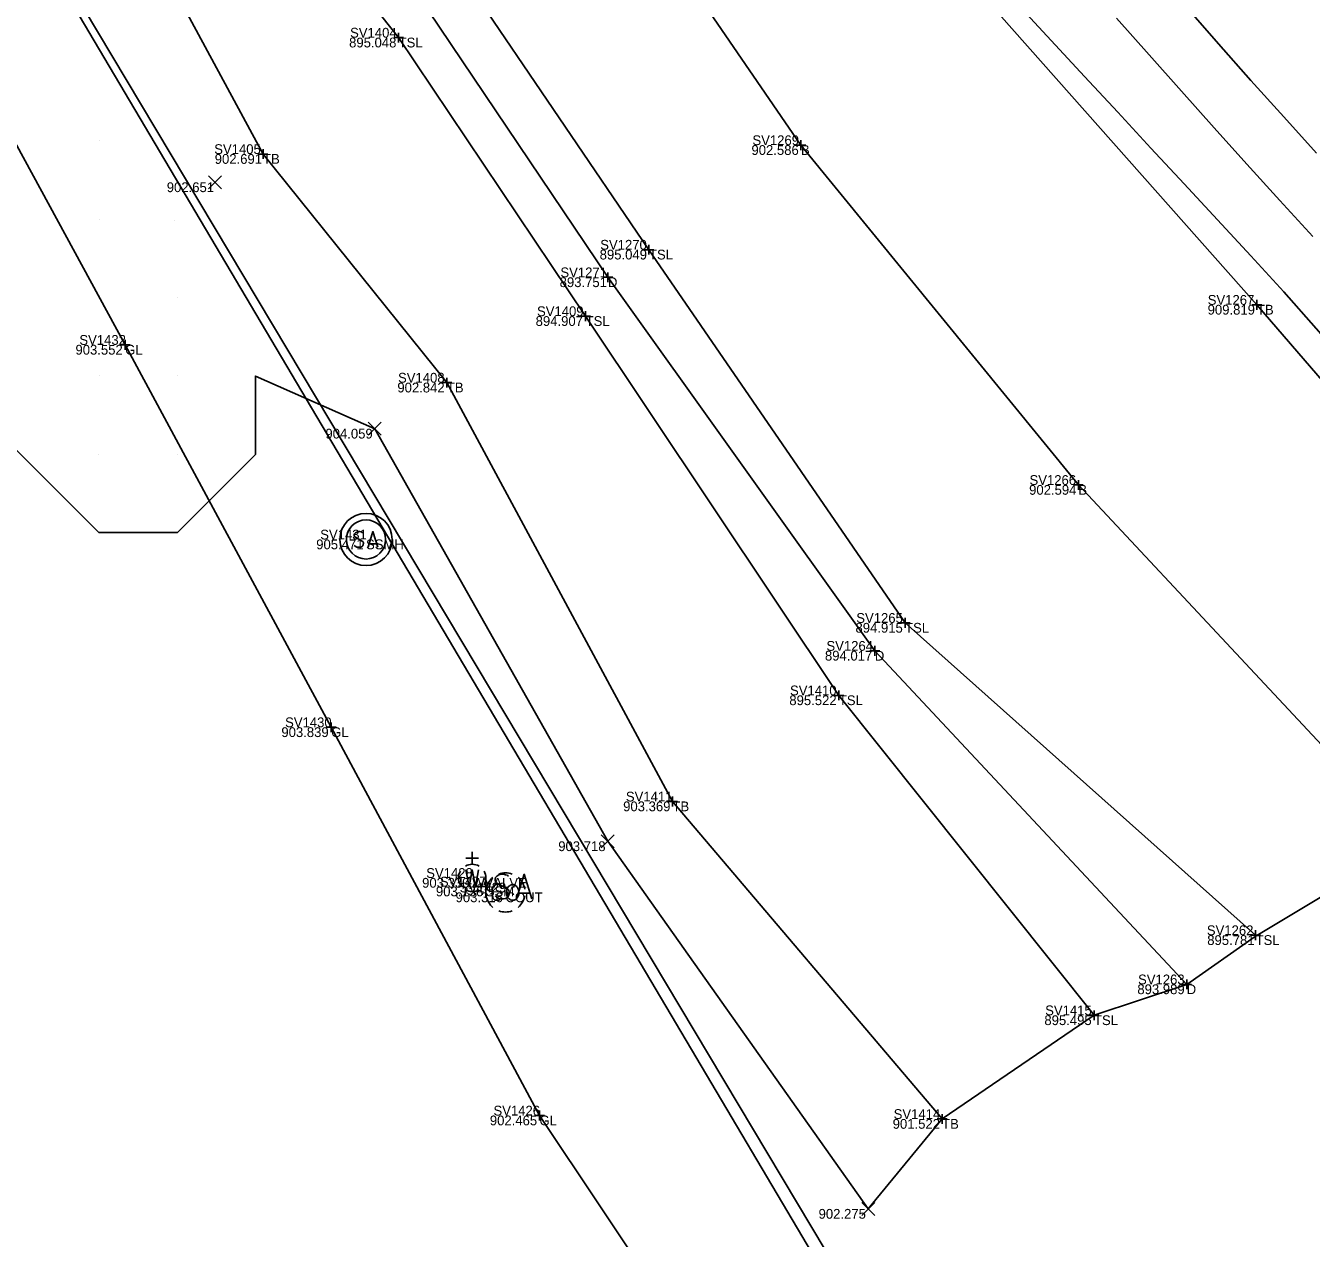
# Model space of a CAD drawing. Extents: x 1918148 to 1919797, y 624701 to 627089.
# Drawn here: x 1918904 to 1919035.3, y 625387.1 to 625511 of the extents above; entities that cross this region are included whole.
import ezdxf

# ---------------------------------------------------------------- set-up
doc = ezdxf.new("R2010")
doc.units = 0
for name, color, linetype in [('DR_X_Cells', 7, 'Continuous'), ('DR_X_Ditch', 7, 'Continuous'), ('DT_X_Terrain_Boundary', 7, 'Continuous'), ('GK_Drainage_Nodes', 7, 'Continuous'), ('Ground Shots', 7, 'Continuous'), ('PM_X_Edge_Line', 7, 'Continuous'), ('PV_X_Shoulder_Aggregate', 7, 'Continuous'), ('RD_X_Concrete_Pad', 7, 'Continuous'), ('RD_X_Fence', 7, 'Continuous'), ('SV_X_Break_Lines', 7, 'Continuous'), ('SV_X_Random_Point', 7, 'Continuous'), ('SV_X_Shot_Marker', 7, 'Continuous'), ('SV_X_Text_Comment', 7, 'Continuous'), ('SV_X_Text_Elevation', 7, 'Continuous'), ('SV_X_Text_Name', 7, 'Continuous'), ('SV_X_Toe_of_Slope', 7, 'Continuous'), ('SV_X_Top_of_Bank', 7, 'Continuous'), ('UT_X_Gas', 7, 'Continuous'), ('UT_X_Overhead_Combined', 7, 'Continuous'), ('UT_X_Sanitary_Cells', 7, 'Continuous'), ('UT_X_Water_Cells', 7, 'Continuous')]:
    doc.layers.add(name, color=color, linetype=linetype)

msp = doc.modelspace()

# ---------------------------------------------------------------- linework, layer by layer
at = {"layer": 'DR_X_Cells'}
msp.add_line((1918953, 625422.45), (1918953, 625422.45), dxfattribs=at)
for points in [[(1918952.59, 625422.93), (1918952.52, 625423.07), (1918952.46, 625423.15), (1918952.4, 625423.2), (1918952.35, 625423.22), (1918952.21, 625423.25), (1918952.07, 625423.25), (1918951.89, 625423.2), (1918951.79, 625423.12), (1918951.74, 625423.06), (1918951.69, 625422.97), (1918951.65, 625422.83), (1918951.64, 625422.58), (1918951.64, 625422.39), (1918951.64, 625422.27), (1918951.65, 625422.15), (1918951.69, 625421.95), (1918951.7, 625421.91), (1918951.75, 625421.82), (1918951.8, 625421.76), (1918951.89, 625421.7), (1918951.97, 625421.67), (1918952.07, 625421.65), (1918952.18, 625421.65), (1918952.3, 625421.66), (1918952.33, 625421.67), (1918952.38, 625421.7), (1918952.43, 625421.75), (1918952.5, 625421.81), (1918952.55, 625421.89), (1918952.59, 625421.95)], [(1918953.61, 625423.24), (1918953.57, 625423.22), (1918953.53, 625423.21), (1918953.47, 625423.17), (1918953.43, 625423.15), (1918953.37, 625423.1), (1918953.32, 625423.05), (1918953.29, 625423.02), (1918953.25, 625422.97), (1918953.19, 625422.84), (1918953.14, 625422.72), (1918953.11, 625422.61), (1918953.1, 625422.44), (1918953.11, 625422.27), (1918953.15, 625422.14), (1918953.19, 625422.04), (1918953.22, 625421.99), (1918953.25, 625421.93), (1918953.3, 625421.86), (1918953.34, 625421.82), (1918953.38, 625421.79), (1918953.43, 625421.75), (1918953.49, 625421.71), (1918953.61, 625421.66), (1918953.67, 625421.65), (1918953.79, 625421.65), (1918953.85, 625421.66), (1918953.9, 625421.67), (1918953.96, 625421.7), (1918954.02, 625421.74), (1918954.06, 625421.76), (1918954.1, 625421.79), (1918954.14, 625421.82), (1918954.17, 625421.87), (1918954.2, 625421.91), (1918954.22, 625421.95), (1918954.25, 625421.99), (1918954.29, 625422.06), (1918954.32, 625422.15), (1918954.35, 625422.25), (1918954.36, 625422.34), (1918954.36, 625422.35), (1918954.36, 625422.44), (1918954.36, 625422.52), (1918954.35, 625422.62), (1918954.32, 625422.72), (1918954.3, 625422.79), (1918954.26, 625422.88), (1918954.22, 625422.96), (1918954.16, 625423.03), (1918954.11, 625423.08), (1918954.06, 625423.13), (1918954.01, 625423.17), (1918953.93, 625423.21), (1918953.86, 625423.24), (1918953.78, 625423.25), (1918953.69, 625423.25), (1918953.61, 625423.24)]]:
    msp.add_lwpolyline(points, dxfattribs=at)
for start, end in [(70.0577, 110.1061), (130.0806, 170.0721), (10.0169, 50.0392), (190.0169, 230.0392), (310.0114, 350.0264), (250.0577, 290.0473)]:
    msp.add_arc((1918953, 625422.45), 2, start, end, dxfattribs=at)
at = {"layer": 'DR_X_Ditch'}
msp.add_lwpolyline([(1919022.6, 625413.06), (1918990.74, 625447.13), (1918963.47, 625485.28), (1918945.14, 625512.5), (1918919.46, 625550.94), (1918912.25, 625562.33), (1918904.47, 625574.16)], dxfattribs=at)
at = {"layer": 'DT_X_Terrain_Boundary'}
msp.add_lwpolyline([(1918871.72, 625515.38), (1918879.45, 625499.23), (1918887.28, 625491.32), (1918895.46, 625475.2), (1918903.47, 625467.18), (1918911.46, 625459.22), (1918919.47, 625459.21), (1918927.47, 625467.19), (1918927.45, 625475.19), (1918939.64, 625469.81), (1918963.45, 625427.67), (1918990.06, 625390.12), (1918997.61, 625399.31), (1919013.13, 625409.9), (1919022.6, 625413.06), (1919029.61, 625417.96), (1919045.66, 625427.6)], dxfattribs=at)
at = {"layer": 'GK_Drainage_Nodes'}
for p, q in [((1918938.75, 625460.5), (1918938.75, 625460.5)), ((1918938.75, 625458.5), (1918938.75, 625458.5)), ((1918938.75, 625458.5), (1918938.75, 625458.5)), ((1918938.75, 625458.5), (1918938.75, 625458.5)), ((1918938.75, 625456.5), (1918938.75, 625456.5))]:
    msp.add_line(p, q, dxfattribs=at)
msp.add_circle((1918938.75, 625458.5), 2, dxfattribs=at)
at = {"layer": 'Ground Shots'}
for p, q in [((1918911.53, 625499.21), (1918911.53, 625499.21)), ((1918911.48, 625491.2), (1918911.48, 625491.2)), ((1918919.17, 625491.05), (1918919.17, 625491.05)), ((1918911.48, 625483.22), (1918911.48, 625483.22)), ((1918919.44, 625483.24), (1918919.44, 625483.24)), ((1918911.47, 625475.21), (1918911.47, 625475.21)), ((1918919.44, 625475.23), (1918919.44, 625475.23)), ((1918927.45, 625475.19), (1918927.45, 625475.19)), ((1918911.45, 625467.19), (1918911.45, 625467.19)), ((1918919.48, 625467.21), (1918919.48, 625467.21)), ((1918927.47, 625467.19), (1918927.47, 625467.19)), ((1918911.46, 625459.22), (1918911.46, 625459.22)), ((1918919.47, 625459.21), (1918919.47, 625459.21))]:
    msp.add_line(p, q, dxfattribs=at)
at = {"layer": 'PM_X_Edge_Line'}
msp.add_lwpolyline([(1919022.56, 625512.89), (1919025.85, 625509.13), (1919029.16, 625505.38), (1919032.51, 625501.67), (1919035.86, 625497.96)], dxfattribs=at)
at = {"layer": 'PV_X_Shoulder_Aggregate'}
msp.add_lwpolyline([(1919068.79, 625442.49), (1919065.49, 625446.24), (1919062.19, 625450), (1919058.9, 625453.75), (1919055.6, 625457.51), (1919052.3, 625461.26), (1919049.01, 625465.02), (1919045.71, 625468.77), (1919042.42, 625472.53), (1919039.12, 625476.29), (1919035.82, 625480.04), (1919032.53, 625483.8), (1919029.14, 625487.48), (1919025.75, 625491.14), (1919022.35, 625494.81), (1919018.95, 625498.47), (1919015.55, 625502.14), (1919012.16, 625505.8), (1919008.76, 625509.47), (1919005.36, 625513.13)], dxfattribs=at)
at = {"layer": 'RD_X_Concrete_Pad'}
msp.add_lwpolyline([(1919015.43, 625511.75), (1919018.75, 625508.01), (1919022.07, 625504.28), (1919025.4, 625500.55), (1919028.76, 625496.84), (1919032.12, 625493.14), (1919035.49, 625489.45)], dxfattribs=at)
at = {"layer": 'RD_X_Fence'}
msp.add_lwpolyline([(1918745.79, 625786.43), (1918772.78, 625741.75), (1918796.76, 625701.53), (1918837.42, 625633.44), (1918845.82, 625619.99), (1919000.61, 625360.91)], dxfattribs=at)
at = {"layer": 'SV_X_Break_Lines'}
msp.add_lwpolyline([(1919045.66, 625427.6), (1919011.53, 625464.07), (1918983.19, 625498.78), (1918965.77, 625524.18), (1918940.24, 625565.26), (1918931.64, 625587.04), (1918915.78, 625618.09), (1918902.81, 625643.72), (1918894.51, 625661.89), (1918884.61, 625712.49), (1918865.54, 625771.79)], dxfattribs=at)
at = {"layer": 'SV_X_Random_Point'}
for p, q in [((1918922.66, 625494.31), (1918923.99, 625495.65)), ((1918922.66, 625495.65), (1918923.99, 625494.31)), ((1918938.98, 625469.14), (1918940.31, 625470.47)), ((1918938.98, 625470.47), (1918940.31, 625469.14)), ((1918962.78, 625427.01), (1918964.11, 625428.34)), ((1918962.78, 625428.34), (1918964.11, 625427.01)), ((1918989.4, 625389.45), (1918990.73, 625390.79)), ((1918989.4, 625390.79), (1918990.73, 625389.45))]:
    msp.add_line(p, q, dxfattribs=at)
at = {"layer": 'SV_X_Shot_Marker'}
for p, q in [((1918941.58, 625509.76), (1918942.58, 625509.76)), ((1918942.08, 625510.26), (1918942.08, 625509.26)), ((1918942.08, 625509.76), (1918942.08, 625509.76)), ((1918983.19, 625499.28), (1918983.19, 625498.28)), ((1918927.73, 625497.87), (1918928.73, 625497.87)), ((1918928.23, 625498.37), (1918928.23, 625497.37)), ((1918928.23, 625497.87), (1918928.23, 625497.87)), ((1918982.69, 625498.78), (1918983.69, 625498.78)), ((1918983.19, 625498.78), (1918983.19, 625498.78)), ((1918967.66, 625488.6), (1918967.66, 625487.6)), ((1918967.16, 625488.1), (1918968.16, 625488.1)), ((1918967.66, 625488.1), (1918967.66, 625488.1)), ((1918962.97, 625485.28), (1918963.97, 625485.28)), ((1918963.47, 625485.78), (1918963.47, 625484.78)), ((1918963.47, 625485.28), (1918963.47, 625485.28)), ((1919029.28, 625482.47), (1919030.28, 625482.47)), ((1919029.78, 625482.97), (1919029.78, 625481.97)), ((1919029.78, 625482.47), (1919029.78, 625482.47)), ((1918960.69, 625481.31), (1918961.69, 625481.31)), ((1918961.19, 625481.81), (1918961.19, 625480.81)), ((1918961.19, 625481.31), (1918961.19, 625481.31)), ((1918913.64, 625478.38), (1918914.64, 625478.38)), ((1918914.14, 625478.88), (1918914.14, 625477.88)), ((1918914.14, 625478.38), (1918914.14, 625478.38)), ((1918946.51, 625474.52), (1918947.51, 625474.52)), ((1918947.01, 625475.02), (1918947.01, 625474.02)), ((1918947.01, 625474.52), (1918947.01, 625474.52)), ((1919011.03, 625464.07), (1919012.03, 625464.07)), ((1919011.53, 625464.57), (1919011.53, 625463.57)), ((1919011.53, 625464.07), (1919011.53, 625464.07)), ((1918993.33, 625449.98), (1918994.33, 625449.98)), ((1918993.83, 625450.48), (1918993.83, 625449.48)), ((1918993.83, 625449.98), (1918993.83, 625449.98)), ((1918990.24, 625447.13), (1918991.24, 625447.13)), ((1918990.74, 625447.63), (1918990.74, 625446.63)), ((1918990.74, 625447.13), (1918990.74, 625447.13)), ((1918987.06, 625443.08), (1918987.06, 625442.08)), ((1918986.56, 625442.58), (1918987.56, 625442.58)), ((1918987.06, 625442.58), (1918987.06, 625442.58)), ((1918934.69, 625439.32), (1918935.69, 625439.32)), ((1918935.19, 625439.82), (1918935.19, 625438.82)), ((1918935.19, 625439.32), (1918935.19, 625439.32)), ((1918970.06, 625432.24), (1918970.06, 625431.24)), ((1918969.56, 625431.74), (1918970.56, 625431.74)), ((1918970.06, 625431.74), (1918970.06, 625431.74)), ((1919029.14, 625418.08), (1919030.14, 625418.08)), ((1919029.64, 625418.58), (1919029.64, 625417.58)), ((1919029.64, 625418.08), (1919029.64, 625418.08)), ((1919022.1, 625413.06), (1919023.1, 625413.06)), ((1919022.6, 625413.56), (1919022.6, 625412.56)), ((1919022.6, 625413.06), (1919022.6, 625413.06)), ((1919012.63, 625409.9), (1919013.63, 625409.9)), ((1919013.13, 625410.4), (1919013.13, 625409.4)), ((1919013.13, 625409.9), (1919013.13, 625409.9)), ((1918955.97, 625399.66), (1918956.97, 625399.66)), ((1918956.47, 625400.16), (1918956.47, 625399.16)), ((1918956.47, 625399.66), (1918956.47, 625399.66)), ((1918997.11, 625399.31), (1918998.11, 625399.31)), ((1918997.61, 625399.81), (1918997.61, 625398.81)), ((1918997.61, 625399.31), (1918997.61, 625399.31))]:
    msp.add_line(p, q, dxfattribs=at)
at = {"layer": 'SV_X_Toe_of_Slope'}
for points in [[(1919029.64, 625418.08), (1918993.83, 625449.98), (1918967.66, 625488.1), (1918949.31, 625515.09), (1918923.03, 625553.45), (1918914.75, 625563.94), (1918909.61, 625577.64)], [(1918898.69, 625570.33), (1918902.54, 625562.89), (1918917.76, 625540.86), (1918929.73, 625525.32), (1918942.08, 625509.76), (1918961.19, 625481.31), (1918987.06, 625442.58), (1919013.13, 625409.9)]]:
    msp.add_lwpolyline(points, dxfattribs=at)
at = {"layer": 'SV_X_Top_of_Bank'}
for points in [[(1919066.32, 625440.14), (1919029.78, 625482.47), (1919003.4, 625512.19), (1918983.32, 625538.26), (1918960.17, 625575.62), (1918948.94, 625596.56), (1918932.63, 625627.72), (1918922.22, 625652.79), (1918916.09, 625672.67), (1918901.24, 625716.64), (1918882.07, 625777.61)], [(1918890.33, 625565.67), (1918904.69, 625540.71), (1918916.61, 625519.36), (1918928.23, 625497.87), (1918947.01, 625474.52), (1918970.06, 625431.74), (1918997.61, 625399.31)]]:
    msp.add_lwpolyline(points, dxfattribs=at)
at = {"layer": 'UT_X_Gas'}
msp.add_lwpolyline([(1918759.17, 625917.08), (1918754.31, 625900.24), (1918749.45, 625846.76), (1918748.46, 625829), (1918743.94, 625797.46), (1918743.01, 625773.57), (1918765.83, 625740.86), (1918795.68, 625692.78), (1918822.43, 625647.51), (1918838.93, 625617.6), (1918864.37, 625571.21), (1918888.36, 625525.76), (1918914.14, 625478.38), (1918935.19, 625439.32), (1918956.47, 625399.66), (1918975.3, 625371.47), (1919011.93, 625334.48), (1919018.03, 625313.57)], dxfattribs=at)
at = {"layer": 'UT_X_Overhead_Combined'}
msp.add_lwpolyline([(1918749.03, 625800.12), (1918759.42, 625761.9), (1918898.02, 625531.27), (1919016.4, 625331.43)], dxfattribs=at)
at = {"layer": 'UT_X_Sanitary_Cells'}
for p, q in [((1918950.99, 625423.05), (1918950, 625423.05)), ((1918950.99, 625422.05), (1918950.99, 625424.05))]:
    msp.add_line(p, q, dxfattribs=at)
for points in [[(1918938.41, 625459.18), (1918938.39, 625459.21), (1918938.35, 625459.23), (1918938.24, 625459.27), (1918938.1, 625459.3), (1918938, 625459.3), (1918937.96, 625459.3), (1918937.8, 625459.26), (1918937.66, 625459.18), (1918937.57, 625459.08), (1918937.54, 625458.98), (1918937.54, 625458.91), (1918937.57, 625458.8), (1918937.67, 625458.72), (1918938.36, 625458.34), (1918938.43, 625458.29), (1918938.45, 625458.24), (1918938.48, 625458.16), (1918938.48, 625458.09), (1918938.46, 625458.01), (1918938.45, 625457.96), (1918938.43, 625457.9), (1918938.4, 625457.85), (1918938.38, 625457.81), (1918938.34, 625457.77), (1918938.3, 625457.75), (1918938.25, 625457.72), (1918938.21, 625457.71), (1918938.1, 625457.7), (1918937.92, 625457.7), (1918937.81, 625457.72), (1918937.64, 625457.81), (1918937.54, 625457.89)], [(1918938.96, 625457.7), (1918939.46, 625459.3), (1918939.95, 625457.7)], [(1918939.82, 625458.07), (1918939.08, 625458.07)], [(1918953.29, 625424.12), (1918953.25, 625424.16), (1918953.19, 625424.2), (1918953.01, 625424.26), (1918952.8, 625424.3), (1918952.64, 625424.3), (1918952.58, 625424.3), (1918952.33, 625424.24), (1918952.11, 625424.12), (1918951.97, 625423.96), (1918951.93, 625423.8), (1918951.93, 625423.69), (1918951.97, 625423.53), (1918952.13, 625423.39), (1918953.21, 625422.8), (1918953.31, 625422.72), (1918953.35, 625422.64), (1918953.39, 625422.52), (1918953.39, 625422.41), (1918953.37, 625422.29), (1918953.35, 625422.21), (1918953.31, 625422.11), (1918953.27, 625422.03), (1918953.23, 625421.97), (1918953.17, 625421.91), (1918953.11, 625421.87), (1918953.03, 625421.84), (1918952.98, 625421.82), (1918952.8, 625421.8), (1918952.52, 625421.8), (1918952.35, 625421.84), (1918952.09, 625421.97), (1918951.93, 625422.09)], [(1918954.14, 625421.8), (1918954.92, 625424.3), (1918955.69, 625421.8)], [(1918955.5, 625422.39), (1918954.33, 625422.39)]]:
    msp.add_lwpolyline(points, dxfattribs=at)
for radius in [2.67, 2]:
    msp.add_circle((1918938.75, 625458.5), radius, dxfattribs=at)
at = {"layer": 'UT_X_Water_Cells'}
for p, q in [((1918950.23, 625425.96), (1918948.96, 625425.96)), ((1918949.6, 625425.33), (1918949.6, 625426.6)), ((1918949.6, 625423.93), (1918949.6, 625423.93))]:
    msp.add_line(p, q, dxfattribs=at)
msp.add_lwpolyline([(1918948.96, 625424.75), (1918949.28, 625423.02), (1918949.6, 625424.75), (1918949.92, 625423.02), (1918950.23, 625424.75)], dxfattribs=at)
for start, end in [(150.0184, 209.9816), (60.0184, 120.0157), (330.0184, 29.9816), (239.9843, 299.9816)]:
    msp.add_arc((1918949.6, 625423.93), 1.4, start, end, dxfattribs=at)

# ---------------------------------------------------------------- texts
at = {"layer": 'SV_X_Text_Comment'}
for s, p in [('TSL', (1918942.08, 625508.76)), ('TB', (1918928.23, 625496.87)), ('B', (1918983.19, 625497.78)), ('TSL', (1918967.66, 625487.1)), ('D', (1918963.47, 625484.28)), ('TB', (1919029.78, 625481.47)), ('TSL', (1918961.19, 625480.31)), ('GL', (1918914.14, 625477.38)), ('TB', (1918947.01, 625473.52)), ('B', (1919011.53, 625463.07)), ('SSMH', (1918938.75, 625457.5)), ('TSL', (1918993.83, 625448.98)), ('D', (1918990.74, 625446.13)), ('TSL', (1918987.06, 625441.58)), ('GL', (1918935.19, 625438.32)), ('TB', (1918970.06, 625430.74)), ('WVALVE', (1918949.6, 625422.93)), ('SSM', (1918950.99, 625422.05)), ('COUT', (1918953, 625421.45)), ('TSL', (1919029.64, 625417.08)), ('D', (1919022.6, 625412.06)), ('TSL', (1919013.13, 625408.9)), ('GL', (1918956.47, 625398.66)), ('TB', (1918997.61, 625398.31))]:
    msp.add_text(s, height=1, dxfattribs=at).set_placement(p)
at = {"layer": 'SV_X_Text_Elevation'}
for s, p in [('895.048', (1918937.02, 625508.76)), ('902.691', (1918923.29, 625496.87)), ('902.586', (1918978.13, 625497.78)), ('902.651', (1918918.39, 625493.98)), ('895.049', (1918962.62, 625487.1)), ('893.751', (1918958.53, 625484.28)), ('909.819', (1919024.74, 625481.47)), ('894.907', (1918956.08, 625480.31)), ('903.552', (1918909.06, 625477.38)), ('902.842', (1918941.95, 625473.52)), ('904.059', (1918934.6, 625468.81)), ('902.594', (1919006.5, 625463.07)), ('905.471', (1918933.66, 625457.5)), ('894.915', (1918988.76, 625448.98)), ('894.017', (1918985.64, 625446.13)), ('895.522', (1918982, 625441.58)), ('903.839', (1918930.1, 625438.32)), ('903.369', (1918965.02, 625430.74)), ('903.718', (1918958.39, 625426.67)), ('903.330', (1918944.48, 625422.93)), ('903.136', (1918945.89, 625422.05)), ('903.316', (1918947.9, 625421.45)), ('895.781', (1919024.7, 625417.08)), ('893.989', (1919017.56, 625412.06)), ('895.495', (1919008.06, 625408.9)), ('902.465', (1918951.4, 625398.66)), ('901.522', (1918992.56, 625398.31)), ('902.275', (1918984.99, 625389.12))]:
    msp.add_text(s, height=1, dxfattribs=at).set_placement(p)
at = {"layer": 'SV_X_Text_Name'}
for s, p in [('SV1404', (1918937.12, 625509.76)), ('SV1269', (1918978.23, 625498.78)), ('SV1405', (1918923.24, 625497.87)), ('SV1270', (1918962.68, 625488.1)), ('SV1271', (1918958.61, 625485.28)), ('SV1267', (1919024.75, 625482.47)), ('SV1409', (1918956.22, 625481.31)), ('SV1432', (1918909.46, 625478.38)), ('SV1408', (1918942.02, 625474.52)), ('SV1266', (1919006.54, 625464.07)), ('SV1431', (1918934.07, 625458.5)), ('SV1265', (1918988.84, 625449.98)), ('SV1264', (1918985.79, 625447.13)), ('SV1410', (1918982.07, 625442.58)), ('SV1430', (1918930.48, 625439.32)), ('SV1411', (1918965.3, 625431.74)), ('SV1428', (1918944.9, 625423.93)), ('SV1427', (1918946.3, 625423.05)), ('SV1429', (1918948.32, 625422.45)), ('SV1262', (1919024.66, 625418.08)), ('SV1263', (1919017.63, 625413.06)), ('SV1415', (1919008.14, 625409.9)), ('SV1426', (1918951.77, 625399.66)), ('SV1414', (1918992.66, 625399.31))]:
    msp.add_text(s, height=1, dxfattribs=at).set_placement(p)

doc.saveas('drawing.dxf')
